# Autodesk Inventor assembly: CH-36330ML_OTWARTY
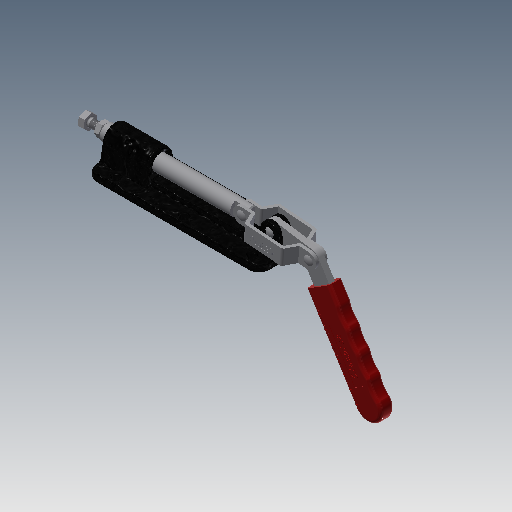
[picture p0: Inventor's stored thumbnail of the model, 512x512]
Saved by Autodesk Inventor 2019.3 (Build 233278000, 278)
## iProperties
Created: 2012-06
Part Number: CH-36330ML_OTWARTY
Material: Ogólny
Document SubType Name: Assembly
Designer: CADENGINEERING4
Sending System: PRO/ENGINEER BY PARAMETRIC TECHNOLOGY CORPORATION, 2007170
Preprocessor: PRO/ENGINEER BY PARAMETRIC TECHNOLOGY CORPORATION, 2007170
Title: CH-36330MLASM0001_ASM
Author: Administrator
Revision Number: 2LAST_VERSION
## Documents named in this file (11)
- D:\Vault_2016\Projekty\STRONA\Push-pull clamp\CH-36330ML\CH-36330ML_OTWARTY.iam
- D:\Vault_2016\Projekty\STRONA\Push-pull clamp\CH-36330ML\36330MLDC.ipt
- D:\Vault_2016\Projekty\STRONA\Push-pull clamp\CH-36330ML\36330-MLSHOUBA.ipt
- D:\Vault_2016\Projekty\STRONA\Push-pull clamp\CH-36330ML\36330MLSHOUB.ipt
- D:\Vault_2016\Projekty\STRONA\Push-pull clamp\CH-36330ML\36330-MLDINGZHOU.ipt
- D:\Vault_2016\Projekty\STRONA\Push-pull clamp\CH-36330ML\36330-MLLIANGA.ipt
- D:\Vault_2016\Projekty\STRONA\Push-pull clamp\CH-36330ML\PRT0001.ipt
- D:\Vault_2016\Projekty\STRONA\Push-pull clamp\CH-36330ML\M8_NUT_____.ipt
- D:\Vault_2016\Projekty\STRONA\Push-pull clamp\CH-36330ML\CH-SA-085012_SPINDLE_SUPPLIED__.ipt
- D:\Vault_2016\Projekty\STRONA\Push-pull clamp\CH-36330ML\PRT0002.ipt
- D:\Vault_2016\Projekty\STRONA\Push-pull clamp\CH-36330ML\PRT0003.ipt
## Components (11 placed, 11 different names)
1. 36330MLDC_0 — Zestawiające:8, Zestawiające:15, Zestawiające:16, Zestawiające:20, Zestawiające:23
2. 36330-MLSHOUBA_1 — Zestawiające:5, Zestawiające:6, Zestawiające:7, Zestawiające:8, Zestawiające:9, Zestawiające:10, Zestawiające:13, Zestawiające:15, Zestawiające:18, Zestawiające:19, Zestawiające:23
3. 36330MLSHOUB_2 — Zestawiające:5, Zestawiające:6, Zestawiające:7
4. 36330-MLDINGZHOU_3 — Zestawiające:3, Zestawiające:4, Zestawiające:14, Zestawiające:16, Zestawiające:17
5. 36330-MLLIANGA_4 — Zestawiające:10, Zestawiające:11, Zestawiające:12, Zestawiające:21, Zestawiające:22
6. PRT0001_5 — Zestawiające:9, Zestawiające:11, Zestawiające:12, Zestawiające:13, Zestawiające:14
7. M8_NUT______6 — Zestawiające:1, Zestawiające:2, Zestawiające:3
8. CH-SA-085012_SPINDLE_SUPPLIED___7 — Zestawiające:1, Zestawiające:2, Zestawiające:4
9. PRT0002_8 — Zestawiające:17, Zestawiające:22
10. PRT0002_9 — Zestawiające:18, Zestawiające:21
11. PRT0003_10 — Zestawiające:19, Zestawiające:20
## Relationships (23: Mate 23)
- Zestawiające:1 [Mate]: M8_NUT______6 ↔ CH-SA-085012_SPINDLE_SUPPLIED___7
- Zestawiające:2 [Mate]: M8_NUT______6 ↔ CH-SA-085012_SPINDLE_SUPPLIED___7
- Zestawiające:3 [Mate]: 36330-MLDINGZHOU_3 ↔ M8_NUT______6
- Zestawiające:4 [Mate]: 36330-MLDINGZHOU_3 ↔ CH-SA-085012_SPINDLE_SUPPLIED___7
- Zestawiające:5 [Mate]: 36330-MLSHOUBA_1 ↔ 36330MLSHOUB_2
- Zestawiające:6 [Mate]: 36330-MLSHOUBA_1 ↔ 36330MLSHOUB_2
- Zestawiające:7 [Mate]: 36330-MLSHOUBA_1 ↔ 36330MLSHOUB_2
- Zestawiające:8 [Mate]: 36330MLDC_0 ↔ 36330-MLSHOUBA_1
- Zestawiające:9 [Mate]: 36330-MLSHOUBA_1 ↔ PRT0001_5
- Zestawiające:10 [Mate]: 36330-MLSHOUBA_1 ↔ 36330-MLLIANGA_4
- Zestawiające:11 [Mate]: 36330-MLLIANGA_4 ↔ PRT0001_5
- Zestawiające:12 [Mate]: 36330-MLLIANGA_4 ↔ PRT0001_5
- Zestawiające:13 [Mate]: 36330-MLSHOUBA_1 ↔ PRT0001_5
- Zestawiające:14 [Mate]: 36330-MLDINGZHOU_3 ↔ PRT0001_5
- Zestawiające:15 [Mate]: 36330MLDC_0 ↔ 36330-MLSHOUBA_1
- Zestawiające:16 [Mate]: 36330MLDC_0 ↔ 36330-MLDINGZHOU_3
- Zestawiające:17 [Mate]: 36330-MLDINGZHOU_3 ↔ PRT0002_8
- Zestawiające:18 [Mate]: 36330-MLSHOUBA_1 ↔ PRT0002_9
- Zestawiające:19 [Mate]: 36330-MLSHOUBA_1 ↔ PRT0003_10
- Zestawiające:20 [Mate]: 36330MLDC_0 ↔ PRT0003_10
- Zestawiające:21 [Mate]: 36330-MLLIANGA_4 ↔ PRT0002_9
- Zestawiające:22 [Mate]: 36330-MLLIANGA_4 ↔ PRT0002_8
- Zestawiające:23 [Mate]: 36330MLDC_0 ↔ 36330-MLSHOUBA_1
